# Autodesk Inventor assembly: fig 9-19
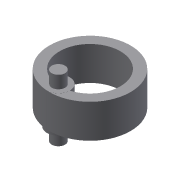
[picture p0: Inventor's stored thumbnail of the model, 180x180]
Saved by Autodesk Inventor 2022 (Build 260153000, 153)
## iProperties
Created: 2002-01
Part Number: fig 9-19
Document SubType Name: Assembly
Designer: ***
Control State: 0
Master: False
Checked Out: False
Shininess: 64.0
Length Units: 11269
Angle Units: 11279
Time Units: 11290
Mass Units: 11283
Length Display Precision: 3
Angle Display Precision: 2
Density: 0.0
Volumn: 0.0
Area: 0.0
PropertySet Name: Model Information
Author: ***
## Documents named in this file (3)
- D:\PROJECTS_2021\Resources\Part Files\c09_Inv_2022_prt\fig 9-19.iam
- D:\PROJECTS_2021\Resources\Part Files\c09_Inv_2022_prt\Part8.ipt
- D:\PROJECTS_2021\Resources\Part Files\c09_Inv_2022_prt\Part9.ipt
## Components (2 placed, 2 different names)
1. Part8:1 — Flush:1
2. Part9:1 — Flush:1
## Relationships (1: Flush 1)
- Flush:1: Part8:1 ↔ Part9:1
